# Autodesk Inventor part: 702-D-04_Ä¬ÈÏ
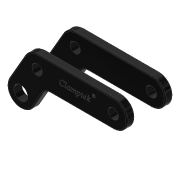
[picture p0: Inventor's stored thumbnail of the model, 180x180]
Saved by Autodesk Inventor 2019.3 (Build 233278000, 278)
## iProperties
Created: 2010-06
Part Number: 702-D-04_Ä¬ÈÏ
Material: Ogólny
Document SubType Name: Modeling
Designer: CADENGINEERING4
Density: 1 g/cm^3
Appearance: Gładki — czarny
Author: CADENGINEERING4
Revision Number: ÈÎºÎ
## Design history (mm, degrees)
feature "NONE"
feature "NONE:1"
node "Bryła1"
node "Bryła2"
